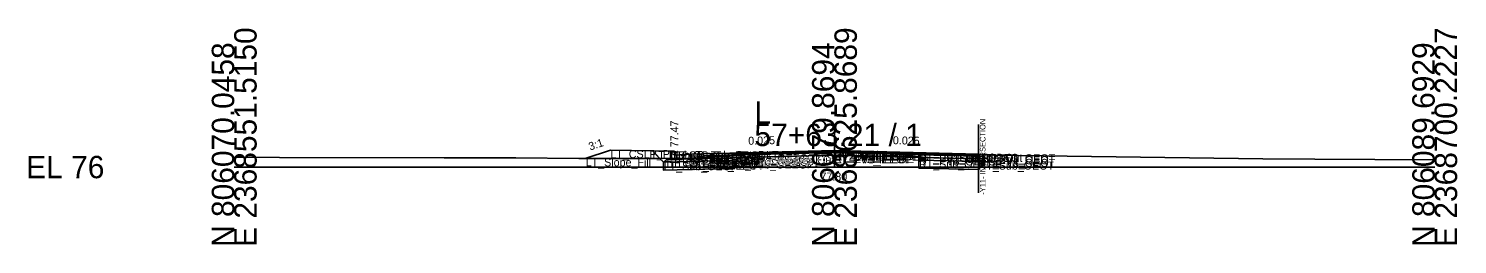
# Model space of a CAD drawing. Extents: x -26 to 8153, y -10 to 9520.
# Drawn here: x 4974.3 to 5152.8, y 6490.3 to 6517.3 of the extents above; entities that cross this region are included whole.
import ezdxf

# ---------------------------------------------------------------- set-up
doc = ezdxf.new("R2010")
doc.units = 0
for name, color, linetype in [('Exist CMT Pavement', 7, 'Continuous'), ('Exist Cross Section Cell', 7, 'Continuous'), ('Exist XS Center Line Elevation Label', 7, 'Continuous'), ('Exist XS Ground Line', 7, 'Continuous'), ('Prop CMT Conc Surface', 7, 'Continuous'), ('Prop CMT Concrete Structures', 7, 'Continuous'), ('Prop CMT Pvmt Course 1', 7, 'Continuous'), ('Prop CMT Pvmt Course 1 CG', 7, 'Continuous'), ('Prop CMT Pvmt Course 1 Wedge', 7, 'Continuous'), ('Prop CMT Pvmt Course 2', 7, 'Continuous'), ('Prop CMT Pvmt Course 2 Wedge', 7, 'Continuous'), ('Prop CMT Pvmt Course 3', 7, 'Continuous'), ('Prop CMT Pvmt Course 3 Wedge', 7, 'Continuous'), ('Prop CMT Pvmt Surface', 7, 'Continuous'), ('Prop CMT Pvmt Wedge Surface 1', 7, 'Continuous'), ('Prop CMT Pvmt Wedge Surface 2', 7, 'Continuous'), ('Prop CMT Pvmt Wedge Surface 3', 7, 'Continuous'), ('Prop CMT Shallow Undercut', 7, 'Continuous'), ('Prop CMT Shallow Undercut Boundary', 7, 'Continuous'), ('Prop CMT Shear Line', 7, 'Continuous'), ('Prop CMT Slope Grass', 7, 'Continuous'), ('Prop CMT Subgrade Earthwork', 7, 'Continuous'), ('Prop XS Earthwork Shape', 7, 'Continuous'), ('Prop XS Hydro Elevations', 7, 'Continuous'), ('Prop XS SE Text', 7, 'Continuous'), ('Prop XS Side Slope Text', 7, 'Continuous'), ('Prop XS Subgrade Earthwork', 7, 'Continuous'), ('Scratch_Level_2', 7, 'Continuous'), ('Scratch_Level_6', 7, 'Continuous')]:
    doc.layers.add(name, color=color, linetype=linetype)

msp = doc.modelspace()

# ---------------------------------------------------------------- linework, layer by layer
at = {"layer": 'Exist CMT Pavement'}
for p, q in [((5061.91, 6501.35), (5064.29, 6501.6)), ((5064.29, 6501.6), (5064.66, 6501.64)), ((5064.66, 6501.64), (5067.81, 6501.69)), ((5067.81, 6501.69), (5074.1, 6501.79)), ((5074.1, 6501.79), (5074.79, 6501.81)), ((5074.79, 6501.81), (5075.23, 6501.8)), ((5075.23, 6501.8), (5086.74, 6501.62))]:
    msp.add_line(p, q, dxfattribs=at)
at = {"layer": 'Exist Cross Section Cell'}
for p, q in [((5075, 6500), (5075, 6505.42)), ((5000, 6500), (5075, 6500)), ((5075, 6500), (5150, 6500))]:
    msp.add_line(p, q, dxfattribs=at)
at = {"layer": 'Exist XS Ground Line'}
for p, q in [((5000, 6501.24), (5005.68, 6501.2)), ((5005.68, 6501.2), (5026.24, 6501.15)), ((5026.24, 6501.15), (5031.15, 6501.17)), ((5031.15, 6501.17), (5035.18, 6501.15)), ((5035.18, 6501.15), (5043.08, 6501.07)), ((5043.08, 6501.07), (5047.25, 6501.06)), ((5047.25, 6501.06), (5053.07, 6501.06)), ((5053.07, 6501.06), (5057.11, 6501.1)), ((5057.11, 6501.1), (5061.28, 6501.35)), ((5061.28, 6501.35), (5061.91, 6501.35)), ((5061.91, 6501.35), (5064.29, 6501.6)), ((5064.29, 6501.6), (5064.66, 6501.64)), ((5064.66, 6501.64), (5067.81, 6501.69)), ((5067.81, 6501.69), (5074.1, 6501.79)), ((5074.1, 6501.79), (5074.79, 6501.81)), ((5074.79, 6501.81), (5075.23, 6501.8)), ((5075.23, 6501.8), (5086.74, 6501.62)), ((5086.74, 6501.62), (5087.41, 6501.6)), ((5087.41, 6501.6), (5088.78, 6501.58)), ((5088.78, 6501.58), (5128.51, 6501.03)), ((5128.51, 6501.03), (5135.02, 6500.97)), ((5135.02, 6500.97), (5150, 6500.89))]:
    msp.add_line(p, q, dxfattribs=at)
at = {"layer": 'Prop CMT Conc Surface'}
for points in [[(5055, 6501.47), (5055, 6501.97), (5054.5, 6501.97)], [(5057, 6501.6), (5055, 6501.47)]]:
    msp.add_lwpolyline(points, dxfattribs=at)
at = {"layer": 'Prop CMT Concrete Structures'}
for points in [[(5057, 6501.6), (5055, 6501.47), (5055, 6501.97), (5054.5, 6501.97)], [(5054.5, 6501.97), (5054.5, 6500.95), (5057, 6501.01)], [(5057, 6501.01), (5057, 6501.6)]]:
    msp.add_lwpolyline(points, dxfattribs=at)
at = {"layer": 'Prop CMT Pvmt Course 1'}
for points in [[(5075, 6502.05), (5057, 6501.6)], [(5057, 6501.6), (5057, 6501.35)], [(5057, 6501.35), (5062.27, 6501.48)], [(5062.27, 6501.6), (5075, 6501.92)], [(5062.27, 6501.48), (5062.27, 6501.6)], [(5075, 6501.8), (5075, 6502.05)], [(5075, 6502.05), (5093, 6501.6)], [(5075, 6501.8), (5075, 6502.05)], [(5075, 6501.92), (5075, 6501.8), (5075, 6501.8)], [(5085.56, 6501.66), (5075, 6501.92)], [(5075, 6501.92), (5075, 6501.8), (5075, 6501.8)], [(5085.56, 6501.53), (5085.56, 6501.66)], [(5093, 6501.35), (5085.56, 6501.53)], [(5093, 6501.6), (5093, 6501.35)]]:
    msp.add_lwpolyline(points, dxfattribs=at)
at = {"layer": 'Prop CMT Pvmt Course 1 CG'}
for points in [[(5057, 6501.01), (5054, 6500.94), (5053.66, 6500.6)], [(5053.66, 6500.6), (5057, 6500.68)], [(5057, 6500.68), (5057, 6501.01)]]:
    msp.add_lwpolyline(points, dxfattribs=at)
at = {"layer": 'Prop CMT Pvmt Course 1 Wedge'}
for points in [[(5075, 6501.92), (5062.27, 6501.6)], [(5075, 6501.92), (5085.56, 6501.66)]]:
    msp.add_lwpolyline(points, dxfattribs=at)
at = {"layer": 'Prop CMT Pvmt Course 2'}
for points in [[(5062.27, 6501.48), (5057, 6501.35)], [(5057, 6501.35), (5057, 6501.02)], [(5057, 6501.02), (5062.27, 6501.15)], [(5062.27, 6501.15), (5062.27, 6501.48)], [(5085.56, 6501.2), (5085.56, 6501.53)], [(5085.56, 6501.53), (5093, 6501.35)], [(5093, 6501.02), (5085.56, 6501.2)], [(5093, 6501.35), (5093, 6501.02)]]:
    msp.add_lwpolyline(points, dxfattribs=at)
at = {"layer": 'Prop CMT Pvmt Course 2 Wedge'}
for points in [[(5075, 6501.8), (5062.27, 6501.48)], [(5075, 6501.8), (5085.56, 6501.53)]]:
    msp.add_lwpolyline(points, dxfattribs=at)
at = {"layer": 'Prop CMT Pvmt Course 3'}
for points in [[(5062.27, 6501.15), (5057, 6501.02)], [(5057, 6501.02), (5057, 6500.68)], [(5057, 6500.68), (5062.27, 6500.82)], [(5062.27, 6500.82), (5062.27, 6501.15)], [(5085.56, 6501.2), (5093, 6501.02)], [(5085.56, 6500.87), (5085.56, 6501.2)], [(5093, 6500.68), (5085.56, 6500.87)], [(5093, 6501.02), (5093, 6500.68)]]:
    msp.add_lwpolyline(points, dxfattribs=at)
at = {"layer": 'Prop CMT Pvmt Course 3 Wedge'}
for points in [[(5075, 6501.47), (5062.27, 6501.15)], [(5075, 6501.47), (5085.56, 6501.2)]]:
    msp.add_lwpolyline(points, dxfattribs=at)
at = {"layer": 'Prop CMT Pvmt Surface'}
for points in [[(5075, 6502.05), (5057, 6501.6)], [(5075, 6502.05), (5093, 6501.6), (5093, 6501.52)]]:
    msp.add_lwpolyline(points, dxfattribs=at)
at = {"layer": 'Prop CMT Pvmt Wedge Surface 1'}
for points in [[(5057, 6501.35), (5057, 6501.6)], [(5062.27, 6501.48), (5057, 6501.35)], [(5075, 6501.92), (5062.27, 6501.6)], [(5062.27, 6501.6), (5062.27, 6501.48)], [(5075, 6501.92), (5085.56, 6501.66)], [(5085.56, 6501.66), (5085.56, 6501.53)], [(5085.56, 6501.53), (5093, 6501.35)], [(5093, 6501.35), (5093, 6501.6)]]:
    msp.add_lwpolyline(points, dxfattribs=at)
at = {"layer": 'Prop CMT Pvmt Wedge Surface 2'}
for points in [[(5075, 6501.8), (5057, 6501.35)], [(5057, 6501.35), (5057, 6501.6)], [(5075, 6501.8), (5093, 6501.35)], [(5093, 6501.35), (5093, 6501.6)]]:
    msp.add_lwpolyline(points, dxfattribs=at)
at = {"layer": 'Prop CMT Pvmt Wedge Surface 3'}
for points in [[(5057, 6501.02), (5057, 6501.6)], [(5075, 6501.47), (5057, 6501.02)], [(5075, 6501.47), (5093, 6501.02)], [(5093, 6501.02), (5093, 6501.6)]]:
    msp.add_lwpolyline(points, dxfattribs=at)
at = {"layer": 'Prop CMT Shallow Undercut'}
for p, q in [((5062.27, 6500.82), (5053.66, 6500.6)), ((5053.66, 6500.6), (5053.66, 6499.6)), ((5062.27, 6499.82), (5062.27, 6500.82)), ((5093, 6500.68), (5085.56, 6500.87)), ((5085.56, 6500.87), (5085.56, 6499.87)), ((5093, 6499.68), (5093, 6500.68)), ((5053.66, 6499.6), (5062.27, 6499.82)), ((5085.56, 6499.87), (5093, 6499.68))]:
    msp.add_line(p, q, dxfattribs=at)
at = {"layer": 'Prop CMT Shallow Undercut Boundary'}
for p, q in [((5053.66, 6500.6), (5053.66, 6499.6)), ((5062.27, 6500.82), (5062.27, 6499.82)), ((5085.56, 6500.87), (5085.56, 6499.87)), ((5093, 6500.68), (5093, 6499.68)), ((5053.66, 6499.6), (5062.27, 6499.82)), ((5093, 6499.68), (5085.56, 6499.87))]:
    msp.add_line(p, q, dxfattribs=at)
at = {"layer": 'Prop CMT Shear Line'}
msp.add_line((5093, 6496.77), (5093, 6505.34), dxfattribs=at)
at = {"layer": 'Prop CMT Slope Grass'}
msp.add_lwpolyline([(5054.5, 6501.97), (5047, 6502.12), (5043.86, 6501.07)], dxfattribs=at)
at = {"layer": 'Prop CMT Subgrade Earthwork'}
for points in [[(5057, 6500.68), (5053.66, 6500.6), (5052.25, 6502.01)], [(5062.27, 6500.82), (5057, 6500.68)], [(5062.27, 6500.82), (5062.27, 6501.39)], [(5085.56, 6500.87), (5085.56, 6501.64)], [(5085.56, 6500.87), (5093, 6500.68)]]:
    msp.add_lwpolyline(points, dxfattribs=at)
at = {"layer": 'Prop XS Earthwork Shape'}
for points in [[(5052.25, 6502.01), (5047, 6502.12), (5043.86, 6501.07), (5047.25, 6501.06), (5053.07, 6501.06), (5053.2, 6501.06)], [(5062.27, 6500.82), (5062.27, 6501.39), (5061.91, 6501.35), (5061.28, 6501.35), (5057.11, 6501.1), (5053.2, 6501.06), (5053.66, 6500.6), (5057, 6500.68)], [(5053.66, 6500.6), (5053.66, 6499.6), (5062.27, 6499.82), (5062.27, 6500.82), (5057, 6500.68)], [(5085.56, 6500.87), (5085.56, 6499.87), (5093, 6499.68), (5093, 6500.68)], [(5085.56, 6500.87), (5085.56, 6499.87), (5093, 6499.68), (5093, 6500.68)]]:
    msp.add_lwpolyline(points, close=True, dxfattribs=at)
at = {"layer": 'Prop XS Subgrade Earthwork'}
for p, q in [((5053.66, 6500.6), (5062.27, 6500.82)), ((5085.56, 6500.87), (5093, 6500.68))]:
    msp.add_line(p, q, dxfattribs=at)
at = {"layer": 'Scratch_Level_6'}
for p, q in [((5062.27, 6500.82), (5053.66, 6500.6)), ((5053.66, 6500.6), (5053.66, 6499.6)), ((5062.27, 6499.82), (5062.27, 6500.82)), ((5093, 6500.68), (5085.56, 6500.87)), ((5085.56, 6500.87), (5085.56, 6499.87)), ((5093, 6499.68), (5093, 6500.68)), ((5053.66, 6499.6), (5062.27, 6499.82)), ((5085.56, 6499.87), (5093, 6499.68))]:
    msp.add_line(p, q, dxfattribs=at)

# ---------------------------------------------------------------- texts
at = {"layer": 'Exist Cross Section Cell'}
for s, p in [('E 2368551.5150', (5002.8, 6490)), ('E 2368625.8689', (5077.8, 6490)), ('E 2368700.2227', (5152.8, 6490)), ('N 806070.0458', (5000, 6490)), ('N 806079.8694', (5075, 6490)), ('N 806089.6929', (5150, 6490))]:
    msp.add_text(s, height=2.8, rotation=90, dxfattribs=at).set_placement(p)
for s, p in [('L', (5065, 6505.42)), ('57+63.21 / 1', (5065, 6502.62)), ('EL 76', (4974, 6498.6))]:
    msp.add_text(s, height=2.8, dxfattribs=at).set_placement(p)
at = {"layer": 'Exist XS Center Line Elevation Label'}
msp.add_text('77.80', height=1, dxfattribs=at).set_placement((5073.25, 6498.3))
at = {"layer": 'Prop CMT Shear Line'}
msp.add_text('-Y11- INTERSECTION', height=0.7, rotation=90, dxfattribs=at).set_placement((5093.87, 6496.53))
at = {"layer": 'Prop XS Hydro Elevations'}
msp.add_text('77.47', height=1, rotation=90, dxfattribs=at).set_placement((5055.5, 6502.47))
at = {"layer": 'Prop XS SE Text'}
for rotation, p in [(1.4321, (5064.24, 6502.78)), (358.5679, (5082.29, 6502.86))]:
    msp.add_text('0.025', height=1, rotation=rotation, dxfattribs=at).set_placement(p)
at = {"layer": 'Prop XS Side Slope Text'}
msp.add_text('3:1', height=1, rotation=18.4349, dxfattribs=at).set_placement((5044.47, 6502.06))
at = {"layer": 'Scratch_Level_2'}
for s, p in [('LT_Slope_Fill', (5043.92, 6500.09)), ('LT_CSLP_Pnt', (5047, 6501.12)), ('LT_Sub_Trench_Out_DLT', (5052.25, 6501.01)), ('LT_Sub_OEOP', (5053.66, 6499.6)), ('LT_CG1_Shelf_Out', (5054, 6499.94)), ('LT_CG_Top_BOC', (5054.5, 6500.97)), ('LT_CG_Bot_BOC', (5054.5, 6499.95)), ('LT_CG_Top_Face', (5055, 6500.97)), ('LT_CG_Top_Gut', (5055, 6500.47)), ('LT_PV1_OEOT', (5057, 6500.6)), ('LT_PV2_OEOT', (5057, 6500.35)), ('LT_PV3_OEOT', (5057, 6500.02)), ('LT_CG_Bot_IE', (5057, 6500.01)), ('LT_Sub_OEOT', (5057, 6499.68)), ('LT_PV1_OEEOP', (5062.27, 6500.6)), ('LT_PV2_OEEOP', (5062.27, 6500.48)), ('LT_PV_OEEOP_EG', (5062.27, 6500.39)), ('LT_PV3_OEEOP', (5062.27, 6500.15)), ('LT_Sub_OEEOP', (5062.27, 6499.82)), ('LT_PV_Sub_Tie_Out', (5062.28, 6500.39)), ('PV1_PGL', (5075, 6501.05)), ('RT_PV1_IEEOP', (5075, 6500.92)), ('LT_PV1_IEEOP', (5075, 6500.92)), ('RT_PV_IEEOP_EG', (5075, 6500.8)), ('LT_PV_IEEOP_EG', (5075, 6500.8)), ('RT_PV2_IEEOP', (5075, 6500.8)), ('LT_PV2_IEEOP', (5075, 6500.8)), ('PV2_PGL', (5075, 6500.8)), ('RT_PV3_IEEOP', (5075, 6500.47)), ('LT_PV3_IEEOP', (5075, 6500.47)), ('RT_PV_Sub_Tie_Out', (5085.55, 6500.65)), ('RT_PV1_OEEOP', (5085.56, 6500.66)), ('RT_PV_OEEOP_EG', (5085.56, 6500.65)), ('RT_PV2_OEEOP', (5085.56, 6500.53)), ('RT_PV3_OEEOP', (5085.56, 6500.2)), ('RT_Sub_OEEOP', (5085.56, 6499.87)), ('RT_PV1_OEOT', (5093, 6500.6)), ('RT_PV2_OEOT', (5093, 6500.35)), ('RT_PV3_OEOT', (5093, 6500.02)), ('RT_Sub_OEOT', (5093, 6499.68))]:
    msp.add_text(s, height=1, dxfattribs=at).set_placement(p)

doc.saveas('drawing.dxf')
